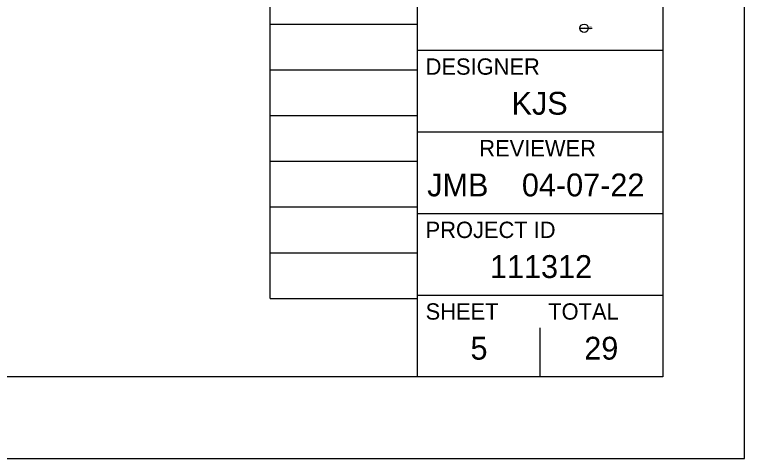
# Model space of a CAD drawing. Extents: x 0 to 63, y -1.2 to 22.
# Drawn here: x 29.536 to 34, y 0 to 2.718 of the extents above; entities that cross this region are included whole.
import ezdxf

# ---------------------------------------------------------------- set-up
doc = ezdxf.new("R2010")
doc.units = 0
for name, color, linetype in [('SH_Border', 7, 'Continuous'), ('SH_Cut_Line', 7, 'Continuous'), ('SH_Data', 7, 'Continuous'), ('SH_Text', 7, 'Continuous')]:
    doc.layers.add(name, color=color, linetype=linetype)

msp = doc.modelspace()

# ---------------------------------------------------------------- linework, layer by layer
at = {"layer": 'SH_Border'}
msp.add_lwpolyline([(0, 0), (34, 0), (34, 22), (0, 22)], close=True, dxfattribs=at)
at = {"layer": 'SH_Cut_Line'}
for p, q in [((32, 0.5), (32, 21.5)), ((32, 2.5), (33.5, 2.5)), ((32, 2), (33.5, 2)), ((32, 1.5), (33.5, 1.5)), ((32, 1), (33.5, 1))]:
    msp.add_line(p, q, dxfattribs=at)
msp.add_lwpolyline([(1.5, 21.5), (33.5, 21.5), (33.5, 0.5), (1.5, 0.5)], close=True, dxfattribs=at)
at = {"layer": 'SH_Data'}
for p, q in [((32.75, 0.5), (32.75, 0.8)), ((32.375, 0.675), (32.375, 0.675))]:
    msp.add_line(p, q, dxfattribs=at)
at = {"layer": 'SH_Text'}
for p, q in [((31.1, 0.98), (31.1, 21.14)), ((32, 0.98), (32, 21.14)), ((31.1, 2.66), (32, 2.66)), ((32.993, 2.6344), (33.0451, 2.6344)), ((33.0193, 2.6344), (33.0688, 2.6344)), ((31.1, 2.38), (32, 2.38)), ((31.1, 2.1), (32, 2.1)), ((31.1, 1.82), (32, 1.82)), ((31.1, 1.54), (32, 1.54)), ((31.1, 1.26), (32, 1.26)), ((31.1, 0.98), (32, 0.98))]:
    msp.add_line(p, q, dxfattribs=at)
msp.add_circle((33.0191, 2.6344), 0.026, dxfattribs=at)

# ---------------------------------------------------------------- texts
at = {"layer": 'SH_Data'}
for s, height, p in [('DESIGNER', 0.1, (32.05, 2.35)), ('KJS', 0.14, (32.5757, 2.105)), ('REVIEWER', 0.1, (32.3783, 1.85)), ('JMB', 0.14, (32.0596, 1.605)), ('04-07-22', 0.14, (32.6389, 1.605)), ('PROJECT ID', 0.1, (32.05, 1.35)), ('111312', 0.14, (32.4435, 1.105)), ('SHEET', 0.1, (32.05, 0.85)), ('TOTAL', 0.1, (32.8, 0.85)), ('5', 0.14, (32.3245, 0.605)), ('29', 0.14, (33.0206, 0.605))]:
    msp.add_text(s, height=height, dxfattribs=at).set_placement(p)
at = {"layer": 'SH_Text'}
for s, p in [('1', (33.0182, 2.641)), ('Drawing', (33.0518, 2.641)), ('1:2', (33.0518, 2.6246))]:
    msp.add_text(s, height=0.00328, dxfattribs=at).set_placement(p)

doc.saveas('drawing.dxf')
